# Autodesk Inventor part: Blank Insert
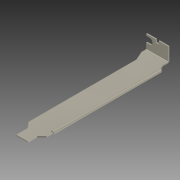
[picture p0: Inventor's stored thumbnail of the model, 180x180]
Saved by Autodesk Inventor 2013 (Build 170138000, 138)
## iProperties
Created: 2007-02
Part Number: Blank Insert
Material: Allgemein
Document SubType Name: Sheet Metal
Designer: Autodesk, Inc.
Mass: 2.38072 g
Surface Area: 50.7843 cm^2
Volume: 2.38072 cm^3
Density: 1 g/cm^3
Sheet Metal Rule: 1 mm
Author: Autodesk, Inc.
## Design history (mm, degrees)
node "Face1"
node "Flange2"
node "Face2"
sketch "Sketch5"
  geometry: L1 (-17.429, 18.5)-(0, 18.5) reference; L2 (0, 18.5)-(0, 0) reference; L3 (0, 0)-(-108, 0) reference; L4 (-12, 18.5)-(-8, 14.35); L5 (-8, 14.35)-(0, 14.35); L6 (0, 4.35)-(-10, 4.35); L7 (-10, 4.35)-(-15, 0)
  constraints: 8 end point, 4 point on line, 2 parallel
  dimensions: "d40" = 8 distance of L4.end L5.end; "d41" = 12 distance from line of L4.start L2; "d42" = 15 distance from line of L2 L7.end; "d43" = 10 distance of L6.start L6.end; "d44" = 10 distance between parallel lines of L6 L5
cut "Cut1" sketch "Sketch5" dims "d45" = 1 (= Thickness), "d46" = 0
sketch "Sketch7"
  geometry: L1 (0, 0)-(0, 19) reference; L2 (0, 9.5)-(-7.53, 9.5); L3 (-2.5, 8.25)-(0, 8.25); L4 (0, 8.25)-(0, 10.75); L5 (0, 10.75)-(-2.5, 10.75); L6 (-2.5, 10.75)-(-2.5, 8.25); L7 (-6.5, 3)-(-1.5, 3); L8 (-1.5, 3)-(-1.5, 0); L9 (-1.5, 0)-(-6.5, 0); L10 (-6.5, 0)-(-6.5, 3); L11 (0, 0)-(-11, 0) reference; C1 r 2.5 at (-4, 3); 2 further points
  constraints: 18 end point, 4 parallel, 3 midpoint, 3 perpendicular, 2 collinear, 2 horizontal, 1 centre point, 1 coincident, 1 point on line, 1 tangent
  dimensions: "d56" = 2.5 distance of L3.start L3.end; "d63" = 5 diameter of C1; "d64" = 3 distance from line of C1.centre L9; "d65" = 4 distance from line of L1 C1.centre
cut "Cut2" sketch "Sketch7" dims "d61" = 1 (= Thickness), "d62" = 0
body "Solid1"
node "Flange1"
sketch "Sketch1"
  geometry: L1 (0, 0)-(-108, 0); L2 (-108, 0)-(-116, -3.5); L3 (-116, -3.5)-(-121, -3.5); L4 (-121, -3.5)-(-121, 15.5); L5 (-121, 15.5)-(-116, 15.5); L6 (-116, 15.5)-(-111.429, 17.5); L7 (-111.429, 17.5)-(0, 17.5); L8 (0, 0)-(0, 17.5); 1 further point
  constraints: 16 end point, 1 coincident, 1 horizontal, 1 parallel, 1 perpendicular
  dimensions: "d1" = 17.5 distance between parallel lines of L1 L7; "d2" = 13 distance from line of L1.end L4; "d3" = 5 distance of L2.end L3.end; "d4" = 5 distance of L4.end L5.end (= d3); "d5" = 19 distance of L3.end L4.end; "d6" = 2 distance between parallel lines of L5 L7; "d7" = 121 distance between parallel lines of L8 L4; "d11" = 9.57143 distance from line of L6.end L4
face "Plate1" dims "Thickness" = 1
sketch "Sketch3"
  geometry: L1 (111.429, 0)-(18.429, 0); L2 (18.429, 0)-(18.429, -1); L3 (18.429, -1)-(111.429, -1); L4 (111.429, -1)-(111.429, 0)
  constraints: 8 end point
face "Plate3" dims "d24" = 1 (= BendReliefWidth), "d25" = 0.5 (= BendReliefDepth), "d26" = 2 (= MinimumRemnant), "d27" = 1 (= BendRadius), "d28" = 93, "d29" = 0, "d30" = 2, "d31" = 90 deg, "d32" = 0.5, "d33" = 4 (= CornerReliefSize), "d34" = 1 (= Thickness), "d66" = 1 (= JacobiRadiusSize), "SeamGap" = 0.01, "Thickness" = 1
bend "Bend1" dims "d24" = 1 (= BendReliefWidth), "d25" = 0.5 (= BendReliefDepth), "d26" = 2 (= MinimumRemnant), "d27" = 1 (= BendRadius), "d30" = 2, "d31" = 90 deg, "d32" = 0.5, "SeamGap" = 0.01, "Thickness" = 1
feature "Corner1" dims "d30" = 2, "d31" = 90 deg, "d33" = 4 (= CornerReliefSize), "d34" = 1 (= Thickness), "d66" = 1 (= JacobiRadiusSize)
sketch "Sketch2"
  geometry: L1 (0, 17.5)-(-17.429, 17.5); L2 (-17.429, 17.5)-(-17.429, 18.5); L3 (-17.429, 18.5)-(0, 18.5); L4 (0, 18.5)-(0, 17.5); L5 (-18.429, 18.5)-(-111.429, 18.5) reference; 1 further point
  constraints: 8 end point, 2 parallel, 1 coincident, 1 collinear, 1 horizontal, 1 perpendicular
face "Plate4" dims "d35" = 1 (= BendRadius), "d38" = 2 (= MinimumRemnant), "SeamGap" = 0.01, "Thickness" = 1
bend "Bend2" dims "d35" = 1 (= BendRadius), "d36" = 1 (= BendReliefWidth), "d37" = 0.5 (= BendReliefDepth), "d38" = 2 (= MinimumRemnant), "d39" = 1 (= BendRadius), "SeamGap" = 0.01, "Thickness" = 1
sketch "Sketch6"
  geometry: L1 through (9.5, 0) direction (-1, 0); L2 through (0, -6.25) direction (0, -1); L3 (0, -12.5)-(19, -12.5); L4 (19, -12.5)-(19, 0)
  constraints: 6 end point, 1 horizontal, 1 perpendicular, 1 vertical
face "Plate5" dims "d47" = 1 (= BendReliefWidth), "d48" = 0.5 (= BendReliefDepth), "d49" = 2 (= MinimumRemnant), "d50" = 1 (= BendRadius), "d51" = 12.5, "d52" = 90 deg, "d53" = 0.5, "d54" = 4 (= CornerReliefSize), "d55" = 1 (= Thickness), "d67" = 1 (= JacobiRadiusSize), "SeamGap" = 0.01, "Thickness" = 1
bend "Bend3" dims "d47" = 1 (= BendReliefWidth), "d48" = 0.5 (= BendReliefDepth), "d49" = 2 (= MinimumRemnant), "d50" = 1 (= BendRadius), "d51" = 12.5, "d52" = 90 deg, "d53" = 0.5, "SeamGap" = 0.01, "Thickness" = 1
feature "Corner2" dims "d51" = 12.5, "d52" = 90 deg, "d54" = 4 (= CornerReliefSize), "d55" = 1 (= Thickness), "d67" = 1 (= JacobiRadiusSize)
other parameters: "BendRadius" = 1 (= Thickness), "BendReliefWidth" = 1 (= Thickness), "BendReliefDepth" = 0.5 (= 0.5 x Thickness), "CornerReliefSize" = 4 (= 4 x Thickness), "MinimumRemnant" = 2 (= 2 x Thickness), "TransitionRadius" = 1 (= BendRadius), "JacobiRadiusSize" = 1 (= Thickness), "d12" = 1 (= BendRadius), "GapSize" = 1 (= Thickness)
